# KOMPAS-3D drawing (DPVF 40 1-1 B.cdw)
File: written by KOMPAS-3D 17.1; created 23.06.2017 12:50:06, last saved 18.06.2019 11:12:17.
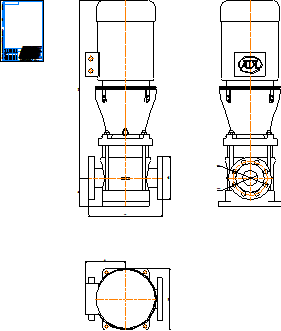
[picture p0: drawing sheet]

Sheet 1: A4, portrait

Title block, sheet 1: name: DPVF 40 1-1 B; material: Внимание! Данный продукт является объектом авторского права ООО «Торговый Дом АДЛ». / Запрещается изменение, копирование, распространение / (в том числе путем копирования на другие сайты и ресурсы в Интернете) / или любое иное использование информации и объектов без предварительного / согласия правообладателя (ООО «Торговый Дом АДЛ»).; scale: 1:1; sheets: 1; organisation: ООО "Торговый дом АДЛ"; sheet format: A4; stored path: C:\Клочков АВ\Насосы\DP PAMS\DPVF 40\Компас 2d\DPVF 40 1-1 B.cdw

Views: Спереди 1
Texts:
  Клочков АВ
  ООО АДЛ ГРУПП
Dimensions and other numbers on the sheet: 365; 197; 306; 209,6; 868,5; 140; 168,1; 76,2; 1:1; 1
